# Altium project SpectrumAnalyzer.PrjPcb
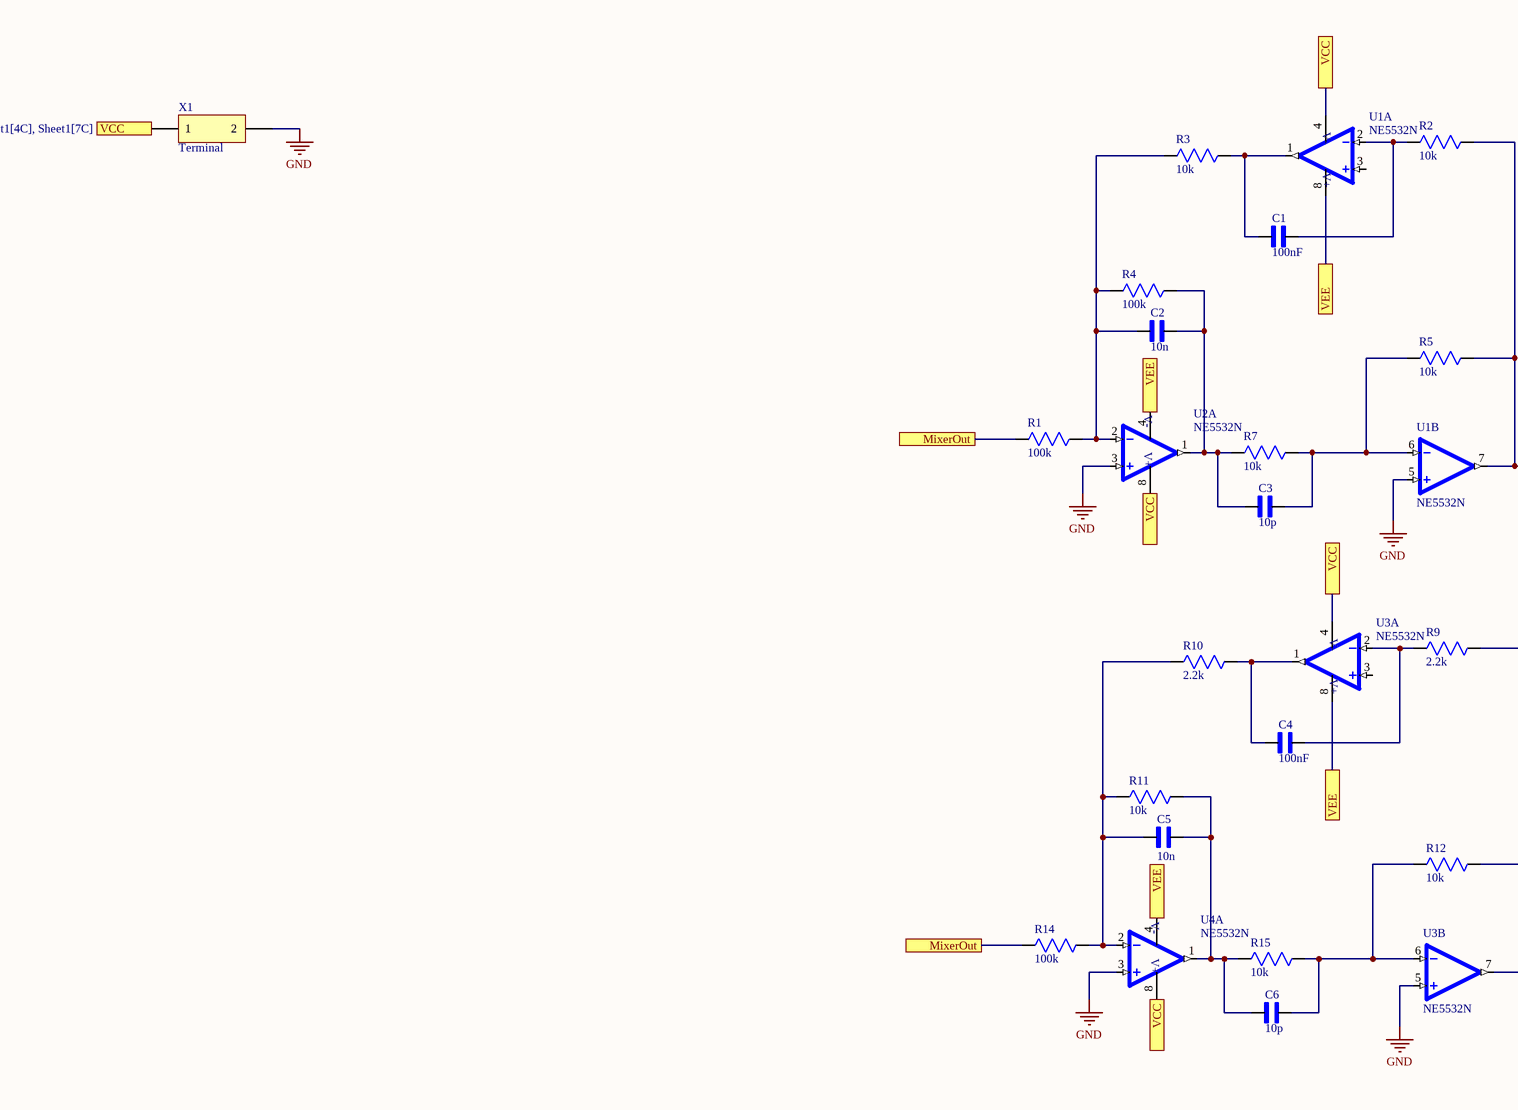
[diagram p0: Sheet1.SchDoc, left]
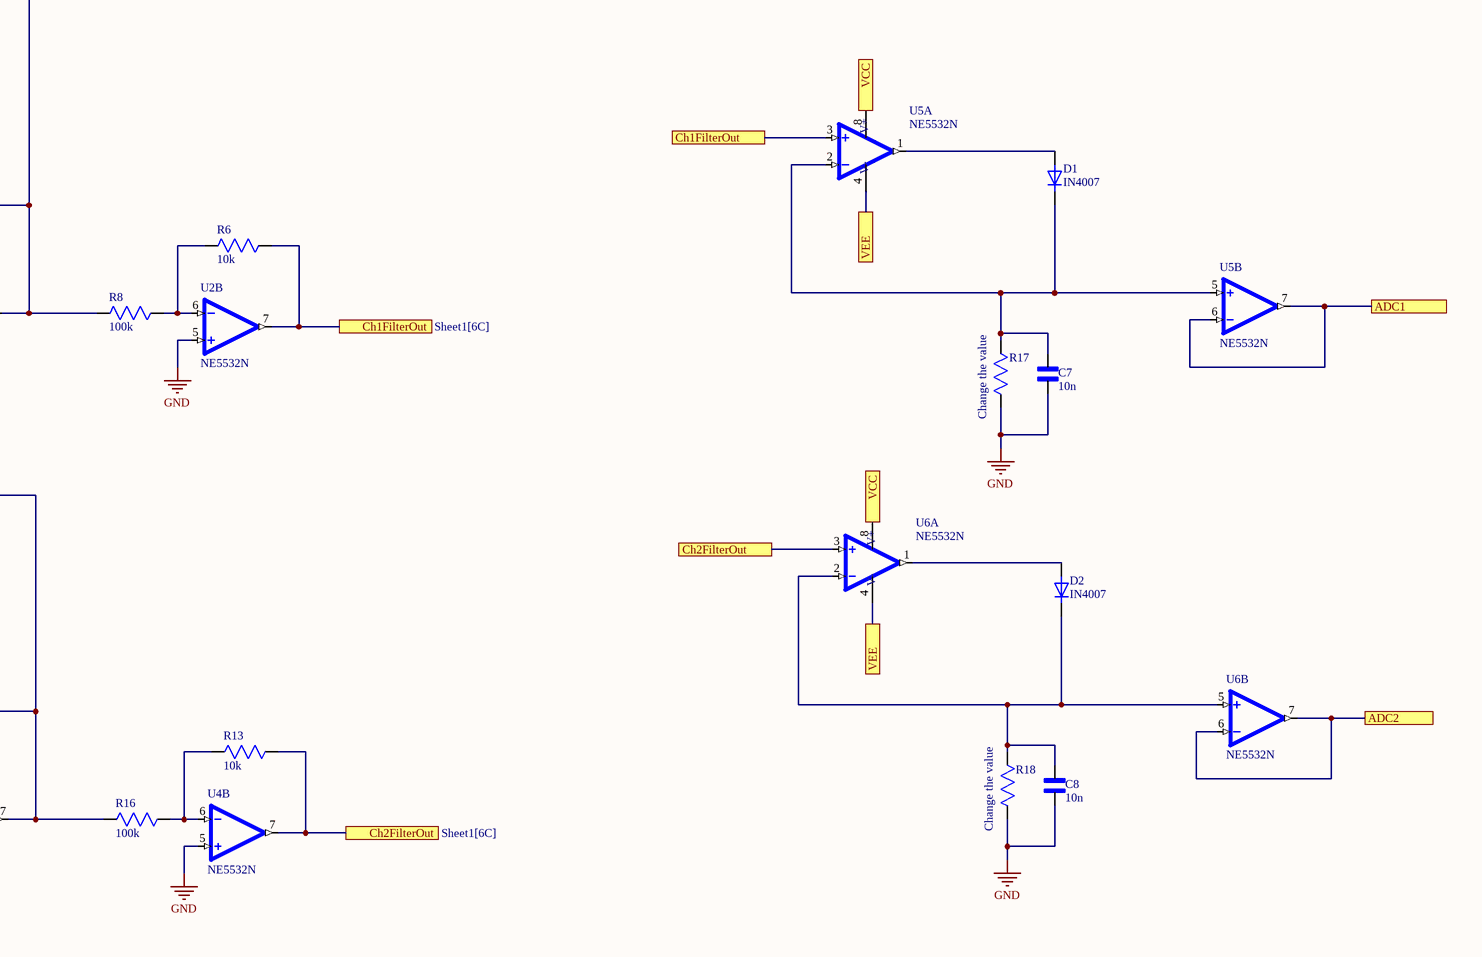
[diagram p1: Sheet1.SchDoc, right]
1 sheet, 35 parts. Net scope: flat (ports and power ports of the same name join across sheets).

## Sheet Sheet1.SchDoc
size A2; SheetNumber: 1; SheetTotal: 1

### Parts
C1  100nF  [CAPC2012X95N]
C2  10n  [CAPC2012X95N]
C3  10p  [CAPC2012X95N]
C4  100nF  [CAPC2012X95N]
C5  10n  [CAPC2012X95N]
C6  10p  [CAPC2012X95N]
C7  10n  [CAPC2012X95N]
C8  10n  [CAPC2012X95N]
D1  IN4007  [DIOAD1070W78L470D235P]
D2  IN4007  [DIOAD1070W78L470D235P]
R1  100k  [RC0805N_YAG-M]
R2  10k  [RC0805N_YAG-M]
R3  10k  [RC0805N_YAG-M]
R4  100k  [RC0805N_YAG-M]
R5  10k  [RC0805N_YAG-M]
R6  10k  [RC0805N_YAG-M]
R7  10k  [RC0805N_YAG-M]
R8  100k  [RC0805N_YAG-M]
R9  2.2k  [RC0805N_YAG-M]
R10  2.2k  [RC0805N_YAG-M]
R11  10k  [RC0805N_YAG-M]
R12  10k  [RC0805N_YAG-M]
R13  10k  [RC0805N_YAG-M]
R14  100k  [RC0805N_YAG-M]
R15  10k  [RC0805N_YAG-M]
R16  100k  [RC0805N_YAG-M]
R17  Change the value  [RC0805N_YAG-M]
R18  Change the value  [RC0805N_YAG-M]
U1  NE5532N  [DIP766W45P254L1016H533Q8]  (parts A,B of 2)
U2  NE5532N  [DIP766W45P254L1016H533Q8]  (parts A,B of 2)
U3  NE5532N  [DIP766W45P254L1016H533Q8]  (parts A,B of 2)
U4  NE5532N  [DIP766W45P254L1016H533Q8]  (parts A,B of 2)
U5  NE5532N  [DIP766W45P254L1016H533Q8]  (parts A,B of 2)
U6  NE5532N  [DIP766W45P254L1016H533Q8]  (parts A,B of 2)
X1  Terminal  [CON_TERMINAL_2POL]

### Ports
ADC1, ADC2, Ch1FilterOut (see Sheet1[5C]), Ch1FilterOut (see Sheet1[6C]), Ch2FilterOut (see Sheet1[5D]), Ch2FilterOut (see Sheet1[6C]), MixerOut (see Sheet1[3C]), MixerOut (see Sheet1[3D]), VCC (see Sheet1[1B], Sheet1[3C], Sheet1[3D], Sheet1[4B], Sheet1[4C], Sheet1[7C]), VCC (see Sheet1[1B], Sheet1[3C], Sheet1[3D], Sheet1[4B], Sheet1[7C]), VCC (see Sheet1[1B], Sheet1[3C], Sheet1[3D], Sheet1[4C], Sheet1[7C]), VCC (see Sheet1[1B], Sheet1[3C], Sheet1[4B], Sheet1[4C], Sheet1[7C]), VCC (see Sheet1[1B], Sheet1[3D], Sheet1[4B], Sheet1[4C], Sheet1[7C]), VCC (see Sheet1[3C], Sheet1[3D], Sheet1[4B], Sheet1[4C], Sheet1[7C]), VEE (see Sheet1[3C], Sheet1[3D], Sheet1[4C], Sheet1[4D], Sheet1[7C]), VEE (see Sheet1[3C], Sheet1[3D], Sheet1[4C], Sheet1[4D], Sheet1[7D]), VEE (see Sheet1[3C], Sheet1[3D], Sheet1[4C], Sheet1[7C], Sheet1[7D]), VEE (see Sheet1[3C], Sheet1[3D], Sheet1[4D], Sheet1[7C], Sheet1[7D]), VEE (see Sheet1[3C], Sheet1[4C], Sheet1[4D], Sheet1[7C], Sheet1[7D]), VEE (see Sheet1[3D], Sheet1[4C], Sheet1[4D], Sheet1[7C], Sheet1[7D])

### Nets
GND: C7.2 C8.2 R17.1 R18.1 U1.5(+INB) U2.3(+INA) U2.5(+INB) U3.5(+INB) U4.3(+INA) U4.5(+INB) X1.2
NetC1_1: C1.1 R3.1 U1.1(OUTA)
NetC1_2: C1.2 R2.2 U1.2(-INA)
NetC2_1: C2.1 R1.1 R3.2 R4.2 U2.2(-INA)
NetC2_2: C2.2 C3.1 R4.1 R7.2 U2.1(OUTA)
NetC3_2: C3.2 R5.2 R7.1 U1.6(-INB)
NetC4_1: C4.1 R10.1 U3.1(OUTA)
NetC4_2: C4.2 R9.2 U3.2(-INA)
NetC5_1: C5.1 R10.2 R11.2 R14.1 U4.2(-INA)
NetC5_2: C5.2 C6.1 R11.1 R15.2 U4.1(OUTA)
NetC6_2: C6.2 R12.2 R15.1 U3.6(-INB)
NetC7_1: C7.1 D1.C R17.2 U5.2(-INA) U5.5(+INB)
NetC8_1: C8.1 D2.C R18.2 U6.2(-INA) U6.5(+INB)
NetD1_A: D1.A U5.1(OUTA)
NetD2_A: D2.A U6.1(OUTA)
NetR1_2: R1.2 R14.2 ; port MixerOut
NetR2_1: R2.1 R5.1 R8.2 U1.7(OUTB)
NetR6_1: R6.1 U2.7(OUTB) U5.3(+INA) ; port Ch1FilterOut
NetR6_2: R6.2 R8.1 U2.6(-INB)
NetR9_1: R9.1 R12.1 R16.2 U3.7(OUTB)
NetR13_1: R13.1 U4.7(OUTB) U6.3(+INA) ; port Ch2FilterOut
NetR13_2: R13.2 R16.1 U4.6(-INB)
NetU1_4: U1.4(V-) U2.8(V+) U3.4(V-) U4.8(V+) U5.8(V+) U6.8(V+) X1.1 ; port VCC
NetU1_8: U1.8(V+) U2.4(V-) U3.8(V+) U4.4(V-) U5.4(V-) U6.4(V-) ; port VEE
NetU5_6: U5.6(-INB) U5.7(OUTB) ; port ADC1
NetU6_6: U6.6(-INB) U6.7(OUTB) ; port ADC2

Not connected (* = marked no-connect by the designer): U1 3(+INA); U3 3(+INA)

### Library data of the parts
C1 C4 = CAP_0805_GENERIC: 0.1 ÂµF Â±10% 50V Ceramic Capacitor X7R 0805 (2012 Metric); MF: Samsung Electro-Mechanics; MP: CL21B104KBCNNNC
C2 C3 C5-C8 = CAP_0805_GENERIC: 0.1 ÂµF Â±10% 50V Ceramic Capacitor X7R 0805 (2012 Metric); Value: 100nF; MF: Samsung Electro-Mechanics; MP: CL21B104KBCNNNC
D1 D2 = IN4007: Diode Standard 1000 V 1A Through Hole DO-204AL (DO-41); MF: Vishay Semiconductor
R1 R4 R8-R10 R14 R16-R18 = RES_0805_GENERIC_1: Description; Manufacturer_Name: Yageo; Manufacturer_Part_Number: RC0805FR-0710KL; Value: 10k
R2 R3 R5-R7 R11-R13 R15 = RES_0805_GENERIC_1: Description; Manufacturer_Name: Yageo; Manufacturer_Part_Number: RC0805FR-0710KL
U1-U6 = NE5532N: IC, OP AMP, DUAL; No. of Amplifiers: 2 Amplifier; Bandwidth: 10MHz; Slew Rate: 8V/Âµs; Supply Voltage Range: Â± 15V; Amplifier Case Style: DIP; No. of Pins: 8Pins; Operating Temperature Min: 0Â°C; Operating Temperature Max: 70Â°C; MSL: -; SVHC: No SVHC (1; MF: Fairchild Semiconductor
X1 = CON_TERMINAL_2POL: Terminal Screw; Manufacturer_Name: Yageo; Manufacturer_Part_Number: RC0805FR-0710KL; Value: 10k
